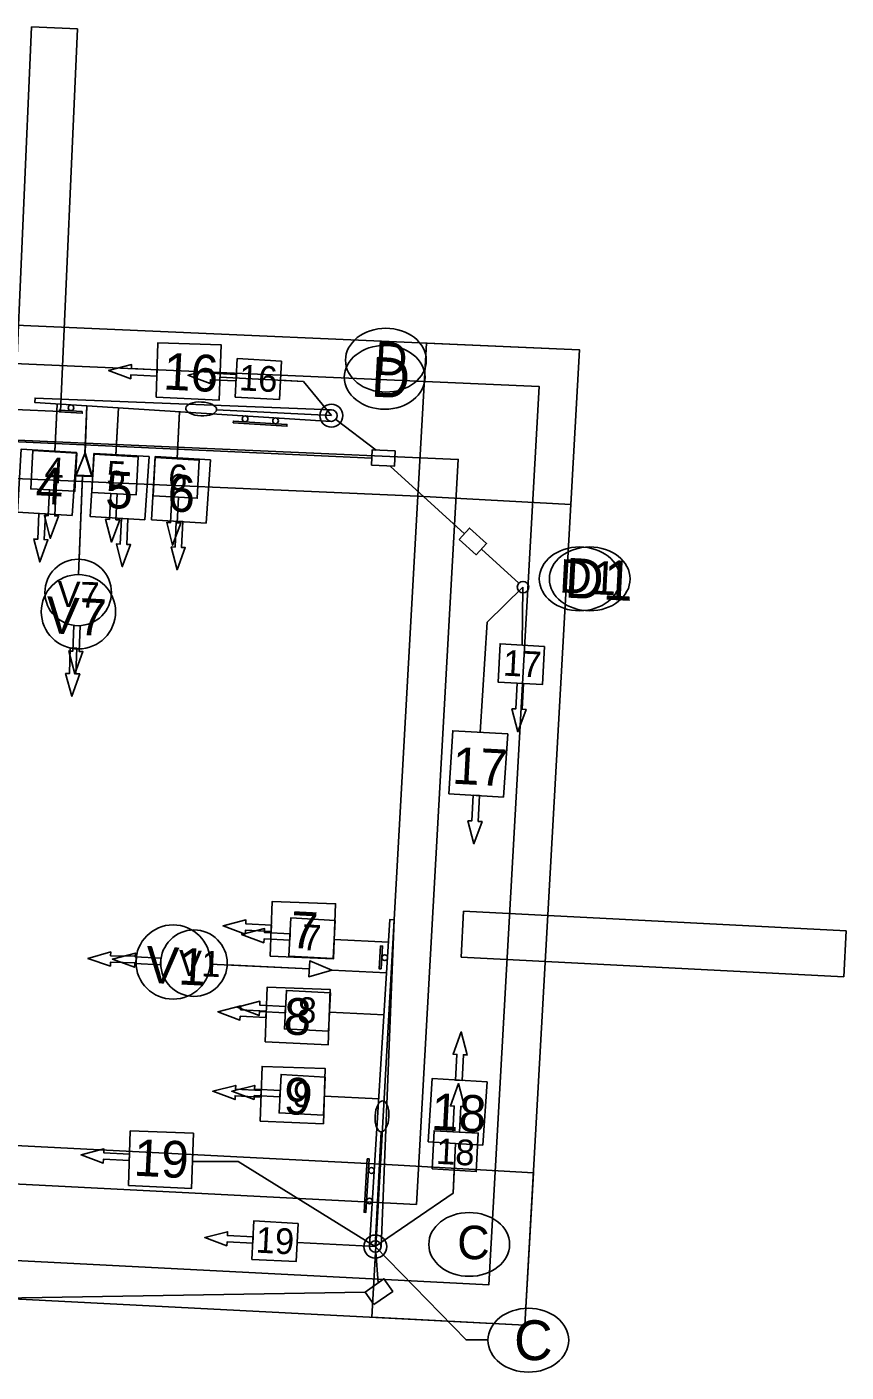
# Model space of a CAD drawing. Extents: x 21 to 686546, y 24 to 735466.
# Drawn here: x 683604.1 to 683711, y 734942.9 to 735118.5 of the extents above; entities that cross this region are included whole.
import ezdxf

# ---------------------------------------------------------------- set-up
doc = ezdxf.new("R2010")
doc.units = 0
for name, color, linetype in [('PEDXLIMITS-PR', 7, 'Continuous'), ('signal wiring diagram', 7, 'Continuous'), ('SIGNAL-PLAN VIEW LABLES', 7, 'Continuous'), ('SIGNAL-PR', 7, 'Continuous'), ('signal-pr-conduit', 7, 'Continuous'), ('Video-Zones-pr', 7, 'Continuous')]:
    doc.layers.add(name, color=color, linetype=linetype)

# ---------------------------------------------------------------- blocks, each defined once
blk = doc.blocks.new('STREET NAME SIGN')
at = {"layer": 'SIGNAL-PR'}
blk.add_lwpolyline([(1.5, 0.96), (1.49, 0.71), (-5.5, 0.9), (-5.5, 1.15)], close=True, dxfattribs=at)
for centre in [(-4, 0.49), (-0.01, 0.37)]:
    blk.add_circle(centre, 0.375, dxfattribs=at)
blk = doc.blocks.new('R10-12 SIGN')
at = {"layer": 'SIGNAL-PR'}
blk.add_lwpolyline([(1.52, 0.75), (-1.48, 0.75), (-1.48, 1), (1.52, 1), (1.52, 0.75)], close=True, dxfattribs=at)
blk.add_circle((0.02, 0.37), 0.375, dxfattribs=at)

msp = doc.modelspace()

# ---------------------------------------------------------------- linework, layer by layer
at = {"layer": 'PEDXLIMITS-PR'}
for points in [[(683525.02, 735082.96), (683676.23, 735076.36), (683669.11, 734949.02), (683518.55, 734956.75)], [(683529.76, 735077.75), (683670.96, 735071.59), (683664.4, 734954.27), (683523.8, 734961.49)], [(683655.13, 735057.26), (683675.1, 735056.15), (683676.23, 735076.36), (683656.25, 735077.23)], [(683654.97, 734964.77), (683660.41, 735062.04), (683539.24, 735067.33), (683534.29, 734970.96)], [(683650.26, 734970.02), (683655.13, 735057.26), (683543.98, 735062.12), (683539.54, 734975.7)], [(683650.26, 734970.02), (683670.22, 734968.9), (683669.11, 734949.02), (683649.14, 734950.05)]]:
    msp.add_lwpolyline(points, close=True, dxfattribs=at)
at = {"layer": 'signal wiring diagram'}
for p, q in [((683640.2, 735072.23), (683643.85, 735067.77)), ((683659.73, 734966.23), (683649.58, 734959.27))]:
    msp.add_line(p, q, dxfattribs=at)
for points in [[(683637.33, 735074.88), (683637.07, 735069.89), (683631.3, 735070.19), (683631.56, 735075.22)], [(683610.63, 735062.88), (683610.37, 735057.89), (683604.6, 735058.19), (683604.86, 735063.22)], [(683611.65, 735062.81), (683612.57, 735059.8), (683610.49, 735059.91)], [(683618.61, 735062.4), (683618.36, 735057.41), (683612.58, 735057.71), (683612.84, 735062.74)], [(683626.6, 735061.97), (683626.34, 735056.98), (683620.57, 735057.28), (683620.83, 735062.31)], [(683671.65, 735037.64), (683671.4, 735032.65), (683665.63, 735032.95), (683665.88, 735037.98)], [(683644.33, 735001.86), (683644.08, 734996.87), (683638.3, 734997.17), (683638.56, 735002.2)], [(683643.91, 734995.37), (683640.89, 734994.49), (683641.02, 734996.57)], [(683643.74, 734992.38), (683643.48, 734987.39), (683637.71, 734987.69), (683637.97, 734992.72)], [(683643.05, 734981.4), (683642.8, 734976.41), (683637.03, 734976.71), (683637.28, 734981.74)], [(683657, 734969.4), (683657.26, 734974.39), (683663.03, 734974.09), (683662.77, 734969.06)], [(683639.51, 734962.29), (683639.25, 734957.3), (683633.48, 734957.6), (683633.74, 734962.63)]]:
    msp.add_lwpolyline(points, close=True, dxfattribs=at)
for points in [[(683628.09, 735073.3), (683628.12, 735073.8), (683625.13, 735073.03), (683628.03, 735071.96), (683628.05, 735072.46), (683631.41, 735072.29), (683631.45, 735073.13), (683628.09, 735073.3)], [(683631.45, 735073.13), (683628.09, 735073.3), (683628.12, 735073.8), (683625.13, 735073.03), (683628.03, 735071.96), (683628.05, 735072.46), (683631.41, 735072.29)], [(683640.2, 735072.23), (683637.2, 735072.39)], [(683608.06, 735069.27), (683607.74, 735063.05)], [(683611.93, 735069.03), (683611.65, 735062.81)], [(683616.05, 735068.77), (683615.73, 735062.57)], [(683624.03, 735068.26), (683623.72, 735062.14)], [(683611.36, 735059.86), (683610.93, 735049.03)], [(683606.89, 735054.71), (683606.39, 735054.73), (683607.16, 735051.74), (683608.24, 735054.64), (683607.73, 735054.66), (683607.9, 735058.02), (683607.07, 735058.06), (683606.89, 735054.71)], [(683607.07, 735058.06), (683606.89, 735054.71), (683606.39, 735054.73), (683607.16, 735051.74), (683608.24, 735054.64), (683607.73, 735054.66), (683607.9, 735058.02)], [(683614.88, 735054.22), (683614.38, 735054.25), (683615.15, 735051.26), (683616.22, 735054.16), (683615.72, 735054.18), (683615.89, 735057.54), (683615.05, 735057.58), (683614.88, 735054.22)], [(683615.05, 735057.58), (683614.88, 735054.22), (683614.38, 735054.25), (683615.15, 735051.26), (683616.22, 735054.16), (683615.72, 735054.18), (683615.89, 735057.54)], [(683622.87, 735053.79), (683622.36, 735053.82), (683623.13, 735050.83), (683624.21, 735053.73), (683623.71, 735053.75), (683623.88, 735057.11), (683623.04, 735057.15), (683622.87, 735053.79)], [(683623.04, 735057.15), (683622.87, 735053.79), (683622.36, 735053.82), (683623.13, 735050.83), (683624.21, 735053.73), (683623.71, 735053.75), (683623.88, 735057.11)], [(683668.86, 735045.36), (683668.77, 735037.83)], [(683610.08, 735037), (683609.57, 735037.02), (683610.38, 735034.04), (683611.42, 735036.95), (683610.92, 735036.97), (683611.05, 735040.33), (683610.21, 735040.36), (683610.08, 735037)], [(683610.21, 735040.36), (683610.08, 735037), (683609.57, 735037.02), (683610.38, 735034.04), (683611.42, 735036.95), (683610.92, 735036.97), (683611.05, 735040.33)], [(683667.92, 735029.47), (683667.42, 735029.49), (683668.19, 735026.5), (683669.26, 735029.4), (683668.76, 735029.42), (683668.93, 735032.78), (683668.09, 735032.82), (683667.92, 735029.47)], [(683668.09, 735032.82), (683667.92, 735029.47), (683667.42, 735029.49), (683668.19, 735026.5), (683669.26, 735029.4), (683668.76, 735029.42), (683668.93, 735032.78)], [(683635.1, 735000.28), (683635.13, 735000.78), (683632.13, 735000.01), (683635.03, 734998.94), (683635.06, 734999.44), (683638.41, 734999.27), (683638.46, 735000.11), (683635.1, 735000.28)], [(683638.46, 735000.11), (683635.1, 735000.28), (683635.13, 735000.78), (683632.13, 735000.01), (683635.03, 734998.94), (683635.06, 734999.44), (683638.41, 734999.27)], [(683651.31, 734999), (683644.2, 734999.37)], [(683618.24, 734997.08), (683618.26, 734997.58), (683615.27, 734996.8), (683618.17, 734995.73), (683618.19, 734996.24), (683621.55, 734996.07), (683621.59, 734996.91), (683618.24, 734997.08)], [(683621.59, 734996.91), (683618.24, 734997.08), (683618.26, 734997.58), (683615.27, 734996.8), (683618.17, 734995.73), (683618.19, 734996.24), (683621.55, 734996.07)], [(683640.96, 734995.52), (683630.25, 734996.05)], [(683651.06, 734995.01), (683643.91, 734995.37)], [(683634.51, 734990.8), (683634.53, 734991.3), (683631.54, 734990.53), (683634.44, 734989.46), (683634.46, 734989.96), (683637.82, 734989.79), (683637.86, 734990.63), (683634.51, 734990.8)], [(683637.86, 734990.63), (683634.51, 734990.8), (683634.53, 734991.3), (683631.54, 734990.53), (683634.44, 734989.46), (683634.46, 734989.96), (683637.82, 734989.79)], [(683650.72, 734989.52), (683643.61, 734989.89)], [(683633.82, 734979.82), (683633.85, 734980.32), (683630.85, 734979.55), (683633.75, 734978.48), (683633.78, 734978.98), (683637.13, 734978.81), (683637.18, 734979.65), (683633.82, 734979.82)], [(683637.18, 734979.65), (683633.82, 734979.82), (683633.85, 734980.32), (683630.85, 734979.55), (683633.75, 734978.48), (683633.78, 734978.98), (683637.13, 734978.81)], [(683660.73, 734977.57), (683661.24, 734977.55), (683660.46, 734980.54), (683659.39, 734977.64), (683659.89, 734977.62), (683659.72, 734974.26), (683660.56, 734974.22), (683660.73, 734977.57)], [(683660.56, 734974.22), (683660.73, 734977.57), (683661.24, 734977.55), (683660.46, 734980.54), (683659.39, 734977.64), (683659.89, 734977.62), (683659.72, 734974.26)], [(683650.03, 734978.54), (683642.93, 734978.91)], [(683659.73, 734966.23), (683659.88, 734969.23)], [(683630.27, 734960.71), (683630.3, 734961.21), (683627.31, 734960.44), (683630.2, 734959.37), (683630.23, 734959.87), (683633.59, 734959.7), (683633.63, 734960.54), (683630.27, 734960.71)], [(683633.63, 734960.54), (683630.27, 734960.71), (683630.3, 734961.21), (683627.31, 734960.44), (683630.2, 734959.37), (683630.23, 734959.87), (683633.59, 734959.7)], [(683649.58, 734959.27), (683639.38, 734959.8)]]:
    msp.add_lwpolyline(points, dxfattribs=at)
for centre in [(683610.8, 735044.68), (683625.91, 734996.27)]:
    msp.add_circle(centre, 4.34, dxfattribs=at)
for centre in [(683650.96, 735075), (683676.25, 735046.45), (683661.84, 734959.55)]:
    msp.add_ellipse(centre, major_axis=(-5.27, 0), ratio=0.790685, dxfattribs=at)
at = {"layer": 'SIGNAL-PLAN VIEW LABLES'}
for p, q in [((683640.2, 735072.23), (683643.85, 735067.77)), ((683625.72, 734970.36), (683631.69, 734970.36)), ((683631.69, 734970.36), (683649.58, 734959.27))]:
    msp.add_line(p, q, dxfattribs=at)
for points in [[(683620.97, 735070.16), (683621.21, 735077.29), (683629.47, 735077), (683629.22, 735069.8)], [(683610, 735054.73), (683602.87, 735055.15), (683603.36, 735063.4), (683610.56, 735062.97)], [(683611.69, 735062.9), (683612.61, 735059.9), (683610.53, 735060)], [(683619.51, 735054.17), (683612.38, 735054.59), (683612.87, 735062.84), (683620.06, 735062.41)], [(683627.49, 735053.74), (683620.37, 735054.16), (683620.86, 735062.41), (683628.05, 735061.98)], [(683666.32, 735017.96), (683659.2, 735018.39), (683659.69, 735026.63), (683666.88, 735026.21)], [(683635.88, 734997.2), (683636.13, 735004.33), (683644.39, 735004.04), (683644.13, 734996.84)], [(683643.91, 734995.37), (683640.89, 734994.49), (683641.02, 734996.57)], [(683635.2, 734985.99), (683635.45, 734993.12), (683643.7, 734992.83), (683643.45, 734985.63)], [(683634.55, 734975.66), (683634.8, 734982.79), (683643.05, 734982.51), (683642.8, 734975.31)], [(683663.63, 734972.53), (683656.5, 734972.95), (683656.99, 734981.2), (683664.18, 734980.77)], [(683617.35, 734967.23), (683617.6, 734974.36), (683625.85, 734974.07), (683625.6, 734966.87)]]:
    msp.add_lwpolyline(points, close=True, dxfattribs=at)
for points in [[(683617.74, 735073.94), (683617.76, 735074.44), (683614.77, 735073.67), (683617.67, 735072.59), (683617.69, 735073.1), (683621.05, 735072.93), (683621.09, 735073.76), (683617.74, 735073.94)], [(683621.09, 735073.76), (683617.74, 735073.94), (683617.76, 735074.44), (683614.77, 735073.67), (683617.67, 735072.59), (683617.69, 735073.1), (683621.05, 735072.93)], [(683640.2, 735072.23), (683629.32, 735072.79)], [(683608.06, 735069.27), (683607.75, 735063.15)], [(683611.93, 735069.03), (683611.69, 735062.9)], [(683616.05, 735068.77), (683615.73, 735062.66)], [(683624.03, 735068.26), (683623.72, 735062.23)], [(683611.37, 735059.96), (683610.86, 735047.01)], [(683605.51, 735051.62), (683605, 735051.65), (683605.78, 735048.66), (683606.85, 735051.56), (683606.35, 735051.58), (683606.52, 735054.94), (683605.68, 735054.98), (683605.51, 735051.62)], [(683605.68, 735054.98), (683605.51, 735051.62), (683605, 735051.65), (683605.78, 735048.66), (683606.85, 735051.56), (683606.35, 735051.58), (683606.52, 735054.94)], [(683616.29, 735050.99), (683615.79, 735051.02), (683616.56, 735048.03), (683617.63, 735050.93), (683617.13, 735050.95), (683617.3, 735054.31), (683616.46, 735054.35), (683616.29, 735050.99)], [(683616.46, 735054.35), (683616.29, 735050.99), (683615.79, 735051.02), (683616.56, 735048.03), (683617.63, 735050.93), (683617.13, 735050.95), (683617.3, 735054.31)], [(683623.44, 735050.61), (683622.94, 735050.63), (683623.71, 735047.64), (683624.78, 735050.54), (683624.28, 735050.56), (683624.45, 735053.92), (683623.61, 735053.96), (683623.44, 735050.61)], [(683623.61, 735053.96), (683623.44, 735050.61), (683622.94, 735050.63), (683623.71, 735047.64), (683624.78, 735050.54), (683624.28, 735050.56), (683624.45, 735053.92)], [(683663.29, 735026.42), (683664.2, 735040.79), (683668.86, 735045.36)], [(683609.66, 735034.08), (683609.15, 735034.1), (683609.98, 735031.12), (683611, 735034.04), (683610.5, 735034.06), (683610.6, 735037.42), (683609.76, 735037.44), (683609.66, 735034.08)], [(683609.76, 735037.44), (683609.66, 735034.08), (683609.15, 735034.1), (683609.98, 735031.12), (683611, 735034.04), (683610.5, 735034.06), (683610.6, 735037.42)], [(683662.18, 735014.84), (683661.68, 735014.86), (683662.45, 735011.87), (683663.52, 735014.77), (683663.02, 735014.79), (683663.19, 735018.15), (683662.35, 735018.19), (683662.18, 735014.84)], [(683662.35, 735018.19), (683662.18, 735014.84), (683661.68, 735014.86), (683662.45, 735011.87), (683663.52, 735014.77), (683663.02, 735014.79), (683663.19, 735018.15)], [(683632.67, 735001.41), (683632.7, 735001.92), (683629.71, 735001.14), (683632.61, 735000.07), (683632.63, 735000.57), (683635.99, 735000.4), (683636.03, 735001.24), (683632.67, 735001.41)], [(683636.03, 735001.24), (683632.67, 735001.41), (683632.7, 735001.92), (683629.71, 735001.14), (683632.61, 735000.07), (683632.63, 735000.57), (683635.99, 735000.4)], [(683651.31, 734999), (683644.2, 734999.37)], [(683615.03, 734997.24), (683615.04, 734997.74), (683612.07, 734996.88), (683615, 734995.9), (683615.01, 734996.4), (683618.37, 734996.33), (683618.39, 734997.17), (683615.03, 734997.24)], [(683618.39, 734997.17), (683615.03, 734997.24), (683615.04, 734997.74), (683612.07, 734996.88), (683615, 734995.9), (683615.01, 734996.4), (683618.37, 734996.33)], [(683640.96, 734995.52), (683628.03, 734996.16)], [(683651.06, 734995.01), (683643.91, 734995.37)], [(683631.99, 734990.19), (683632.02, 734990.7), (683629.03, 734989.92), (683631.92, 734988.85), (683631.95, 734989.35), (683635.3, 734989.18), (683635.35, 734990.02), (683631.99, 734990.19)], [(683635.35, 734990.02), (683631.99, 734990.19), (683632.02, 734990.7), (683629.03, 734989.92), (683631.92, 734988.85), (683631.95, 734989.35), (683635.3, 734989.18)], [(683650.72, 734989.52), (683643.61, 734989.89)], [(683661.08, 734984.32), (683661.58, 734984.3), (683660.81, 734987.29), (683659.74, 734984.39), (683660.24, 734984.36), (683660.07, 734981.01), (683660.91, 734980.97), (683661.08, 734984.32)], [(683660.91, 734980.97), (683661.08, 734984.32), (683661.58, 734984.3), (683660.81, 734987.29), (683659.74, 734984.39), (683660.24, 734984.36), (683660.07, 734981.01)], [(683631.34, 734979.8), (683631.36, 734980.31), (683628.37, 734979.54), (683631.27, 734978.46), (683631.29, 734978.97), (683634.65, 734978.79), (683634.69, 734979.63), (683631.34, 734979.8)], [(683634.69, 734979.63), (683631.34, 734979.8), (683631.36, 734980.31), (683628.37, 734979.54), (683631.27, 734978.46), (683631.29, 734978.97), (683634.65, 734978.79)], [(683650.03, 734978.54), (683642.93, 734978.91)], [(683614.14, 734971.51), (683614.16, 734972.01), (683611.17, 734971.24), (683614.07, 734970.17), (683614.09, 734970.67), (683617.45, 734970.5), (683617.49, 734971.34), (683614.14, 734971.51)], [(683617.49, 734971.34), (683614.14, 734971.51), (683614.16, 734972.01), (683611.17, 734971.24), (683614.07, 734970.17), (683614.09, 734970.67), (683617.45, 734970.5)], [(683649.58, 734959.27), (683659.73, 734966.23), (683660.06, 734972.74)], [(683649.58, 734959.27), (683661.43, 734947.09), (683664.29, 734947.09)]]:
    msp.add_lwpolyline(points, dxfattribs=at)
for centre in [(683610.83, 735042.16), (683623.19, 734996.42)]:
    msp.add_circle(centre, 4.85, dxfattribs=at)
for centre in [(683650.81, 735072.77), (683677.58, 735046.45), (683669.56, 734947.04)]:
    msp.add_ellipse(centre, major_axis=(-5.27, 0), ratio=0.790685, dxfattribs=at)
at = {"layer": 'SIGNAL-PR'}
for p, q in [((683643.85, 735067.77), (683628.87, 735068.53)), ((683649.58, 734959.27), (683650.35, 734974.25))]:
    msp.add_line(p, q, dxfattribs=at)
for points in [[(683643.81, 735068.51), (683605.17, 735070.05), (683605.14, 735069.46), (683643.81, 735067.02)], [(683650.33, 734959.24), (683652.04, 735001.95), (683651.5, 735001.98), (683648.83, 734959.32)]]:
    msp.add_lwpolyline(points, dxfattribs=at)
for points in [[(683649.08, 735061.29), (683652.07, 735061.16), (683652.16, 735063.15), (683649.17, 735063.29)], [(683660.55, 735051.61), (683662.76, 735049.59), (683664.11, 735051.07), (683661.89, 735053.09)], [(683649.4, 734951.69), (683651.85, 734953.42), (683650.7, 734955.06), (683648.25, 734953.33)]]:
    msp.add_lwpolyline(points, close=True, dxfattribs=at)
for centre, radius in [((683643.85, 735067.77), 1.5), ((683643.85, 735067.77), 0.75), ((683668.86, 735045.36), 0.75), ((683649.58, 734959.27), 1.5), ((683649.58, 734959.27), 0.75)]:
    msp.add_circle(centre, radius, dxfattribs=at)
for centre, major_axis in [((683626.85, 735068.64), (2.02, -0.1)), ((683650.46, 734976.27), (-0.11, -2.02))]:
    msp.add_ellipse(centre, major_axis=major_axis, ratio=0.447722, dxfattribs=at)
at = {"layer": 'signal-pr-conduit'}
for points in [[(683644.44, 735067.28), (683649.68, 735063.27)], [(683565.4, 735066.07), (683649.12, 735062.23)], [(683661.22, 735052.35), (683651.53, 735061.18)], [(683668.3, 735045.9), (683663.44, 735050.33)], [(683649.95, 734954.53), (683649.64, 734958.53)], [(683545.41, 734951.61), (683648.26, 734953.31)]]:
    msp.add_lwpolyline(points, dxfattribs=at)
at = {"layer": 'Video-Zones-pr'}
for points in [[(683604.7, 735118.52), (683602.52, 735068.57), (683608.51, 735068.31), (683610.69, 735118.26)], [(683660.8, 734997.06), (683710.73, 734994.5), (683711.04, 735000.49), (683661.1, 735003.05)]]:
    msp.add_lwpolyline(points, close=True, dxfattribs=at)

# ---------------------------------------------------------------- block references
at = {"layer": 'SIGNAL-PR'}
for p, yscale, rotation in [((683609.86, 735069.16), -1.0000000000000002, -3.2616857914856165), ((683651.19, 734996.99), -1, -93.44418492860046)]:
    msp.add_blockref('R10-12 SIGN', p, dxfattribs=dict(at, yscale=yscale, rotation=rotation))
for p, rotation in [((683632.58, 735067.72), 177.99807835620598), ((683649.45, 734969.2), 88.02962556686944)]:
    msp.add_blockref('STREET NAME SIGN', p, dxfattribs=dict(at, rotation=rotation))

# ---------------------------------------------------------------- texts
at = {"layer": 'signal wiring diagram'}
for s, height, rotation, p in [('D', 4.37, 357.0414, (683649.44, 735073.12)), ('16', 3.36, 357.0414, (683631.73, 735071.08)), ('4', 3.36, 357.0414, (683606.36, 735059.01)), ('5', 3.36, 357.0414, (683614.43, 735058.53)), ('6', 3.36, 357.0414, (683622.49, 735058.09)), ('D1', 4.368, 357.0414, (683673.53, 735044.69)), ('V7', 3.36, 358.1697, (683608.02, 735042.81)), ('17', 3.36, 357.0414, (683666.19, 735033.83)), ('7', 3.36, 357.0414, (683639.93, 734998)), ('V1', 3.36, 357.9026, (683623.85, 734994.66)), ('8', 3.36, 357.0414, (683639.34, 734988.52)), ('9', 3.36, 357.0414, (683638.73, 734977.54)), ('18', 3.36, 357.0414, (683657.47, 734970.08)), ('19', 3.36, 357.0414, (683633.91, 734958.49))]:
    msp.add_text(s, height=height, rotation=rotation, dxfattribs=at).set_placement(p)
msp.add_text('C', height=4.37, dxfattribs=at).set_placement((683660.28, 734957.62))
at = {"layer": 'SIGNAL-PLAN VIEW LABLES'}
for s, height, p in [('16', 4.8, (683621.83, 735071.2)), ('D', 5.2, (683648.95, 735070.26)), ('4', 4.8, (683605.17, 735056.29)), ('5', 4.8, (683614.27, 735055.74)), ('6', 4.8, (683622.37, 735055.3)), ('D1', 5.2, (683674.24, 735044.02)), ('V7', 4.8, (683606.49, 735039.38)), ('17', 4.8, (683659.55, 735019.72)), ('7', 4.8, (683638.42, 734998.28)), ('V1', 4.8, (683619.52, 734993.73)), ('8', 4.8, (683637.54, 734987)), ('9', 4.8, (683637.55, 734976.59)), ('18', 4.8, (683656.8, 734974.53)), ('19', 4.8, (683617.97, 734968.54))]:
    msp.add_text(s, height=height, rotation=357.0414, dxfattribs=at).set_placement(p)
msp.add_text('C', height=5.2, dxfattribs=at).set_placement((683667.7, 734944.44))

doc.saveas('drawing.dxf')
